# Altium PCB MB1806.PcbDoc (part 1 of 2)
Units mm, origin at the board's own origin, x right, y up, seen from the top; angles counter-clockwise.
Board outline 43.1 x 47.12 mm, 4 copper layers (Top Layer, Internal 1, Internal 2, Bottom Layer), stack 1.565 mm thick; 88 components, 68 nets, 317 pads, 562 vias.
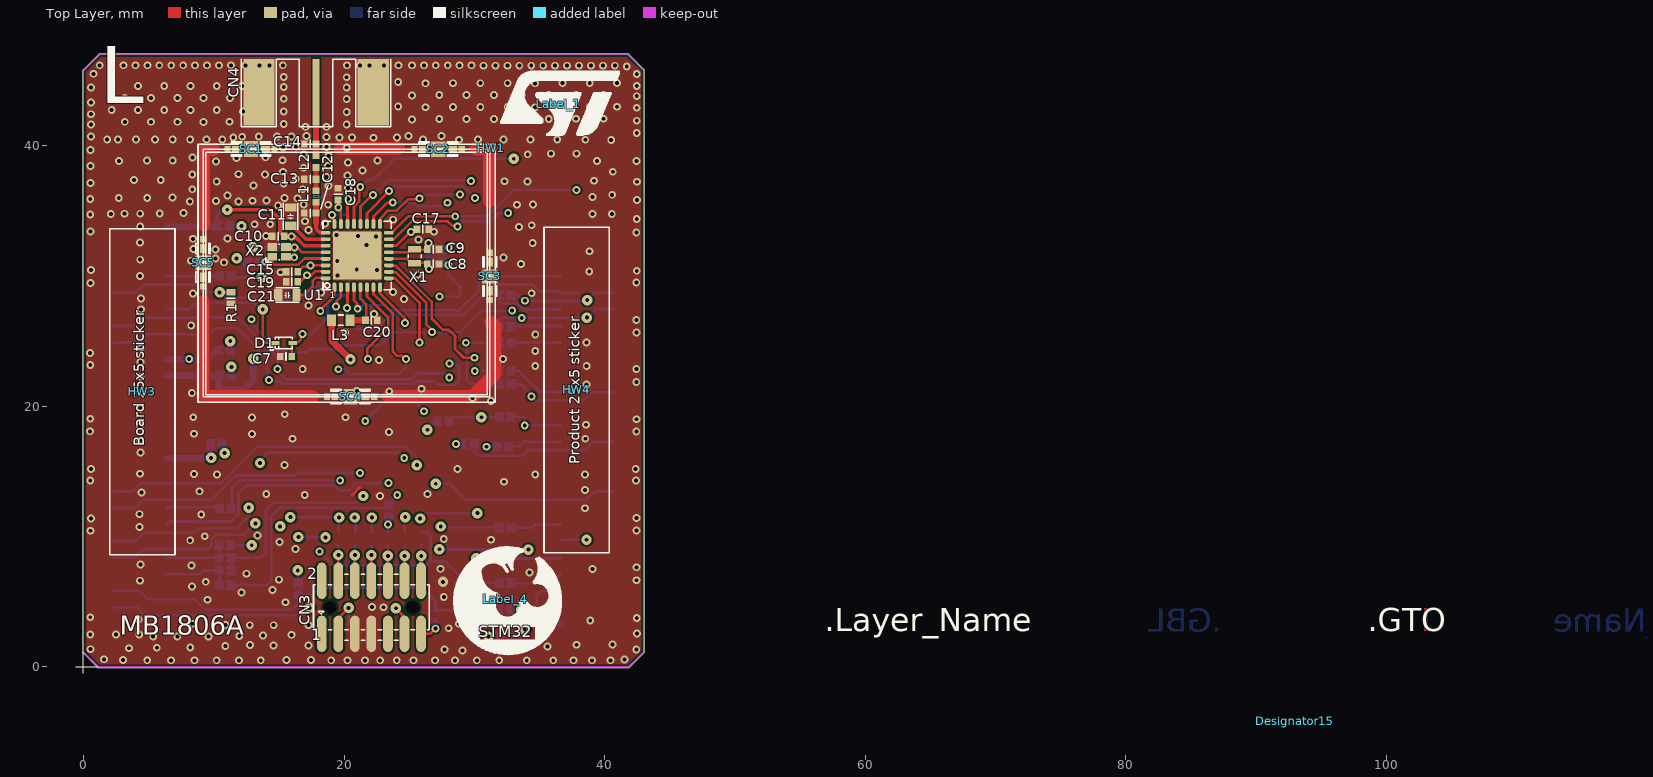
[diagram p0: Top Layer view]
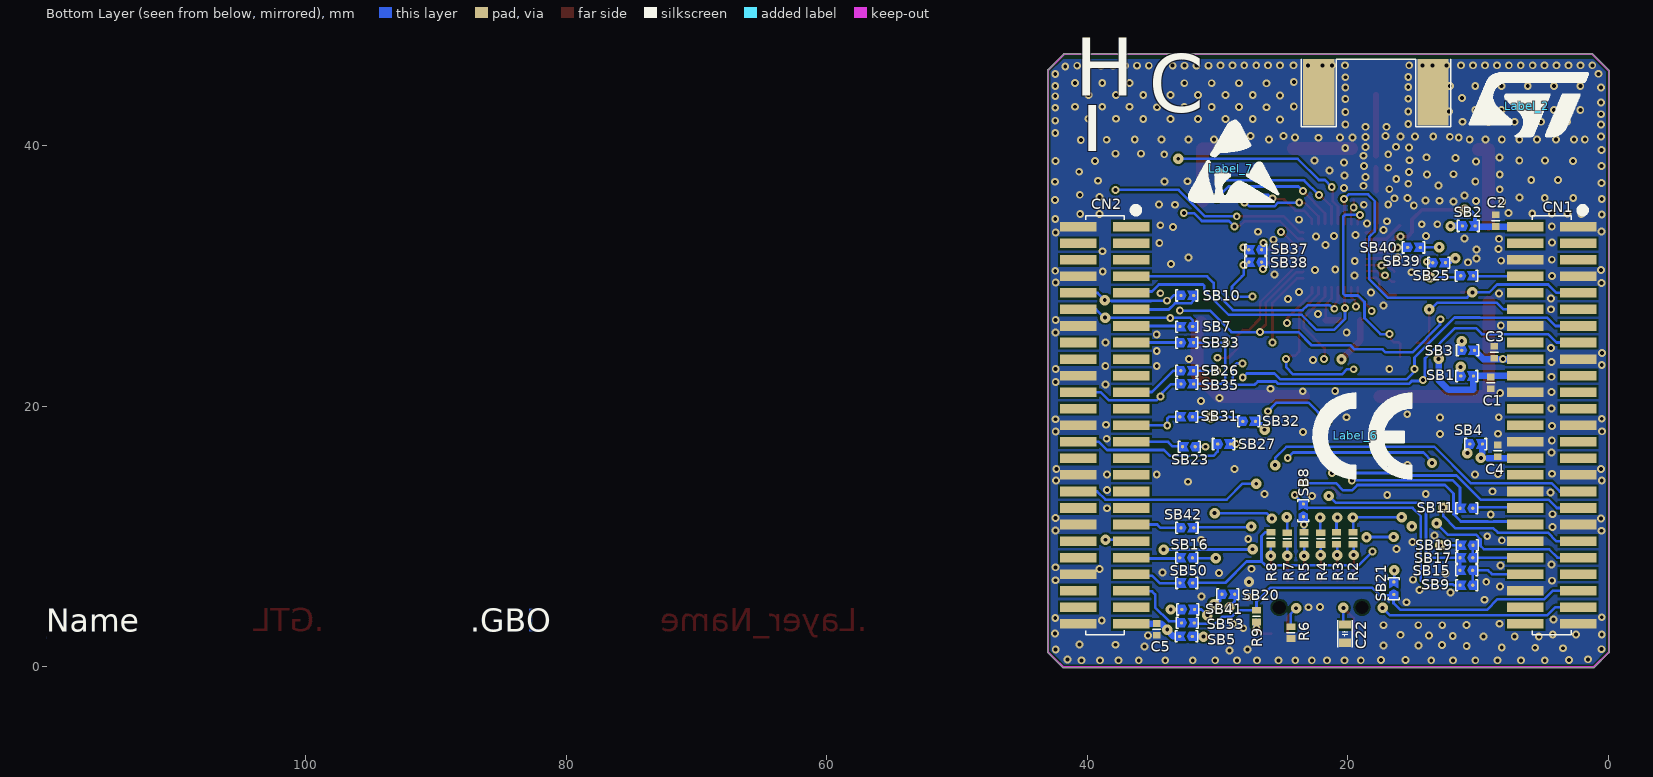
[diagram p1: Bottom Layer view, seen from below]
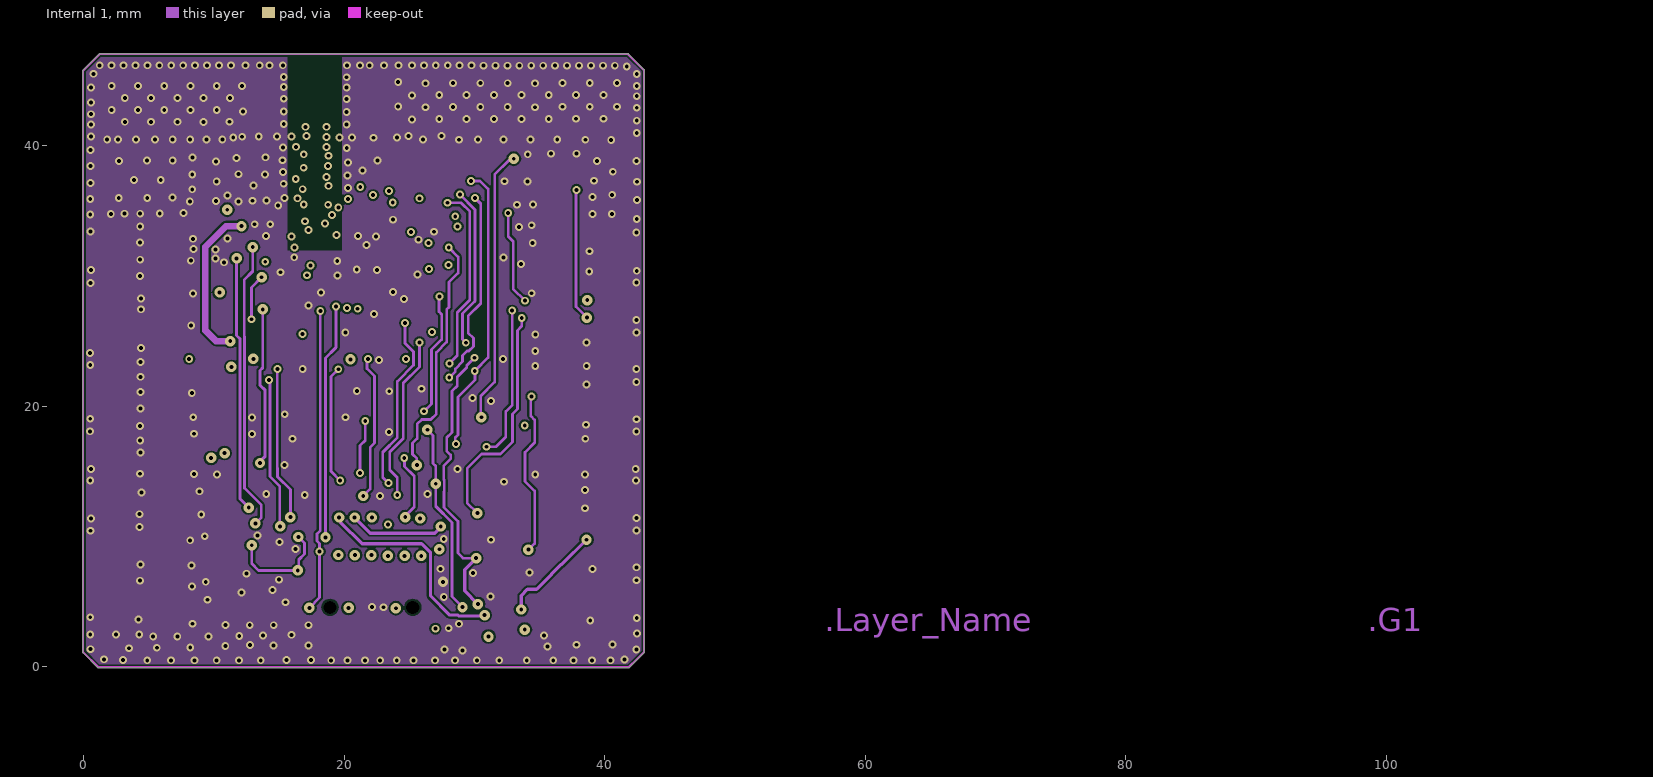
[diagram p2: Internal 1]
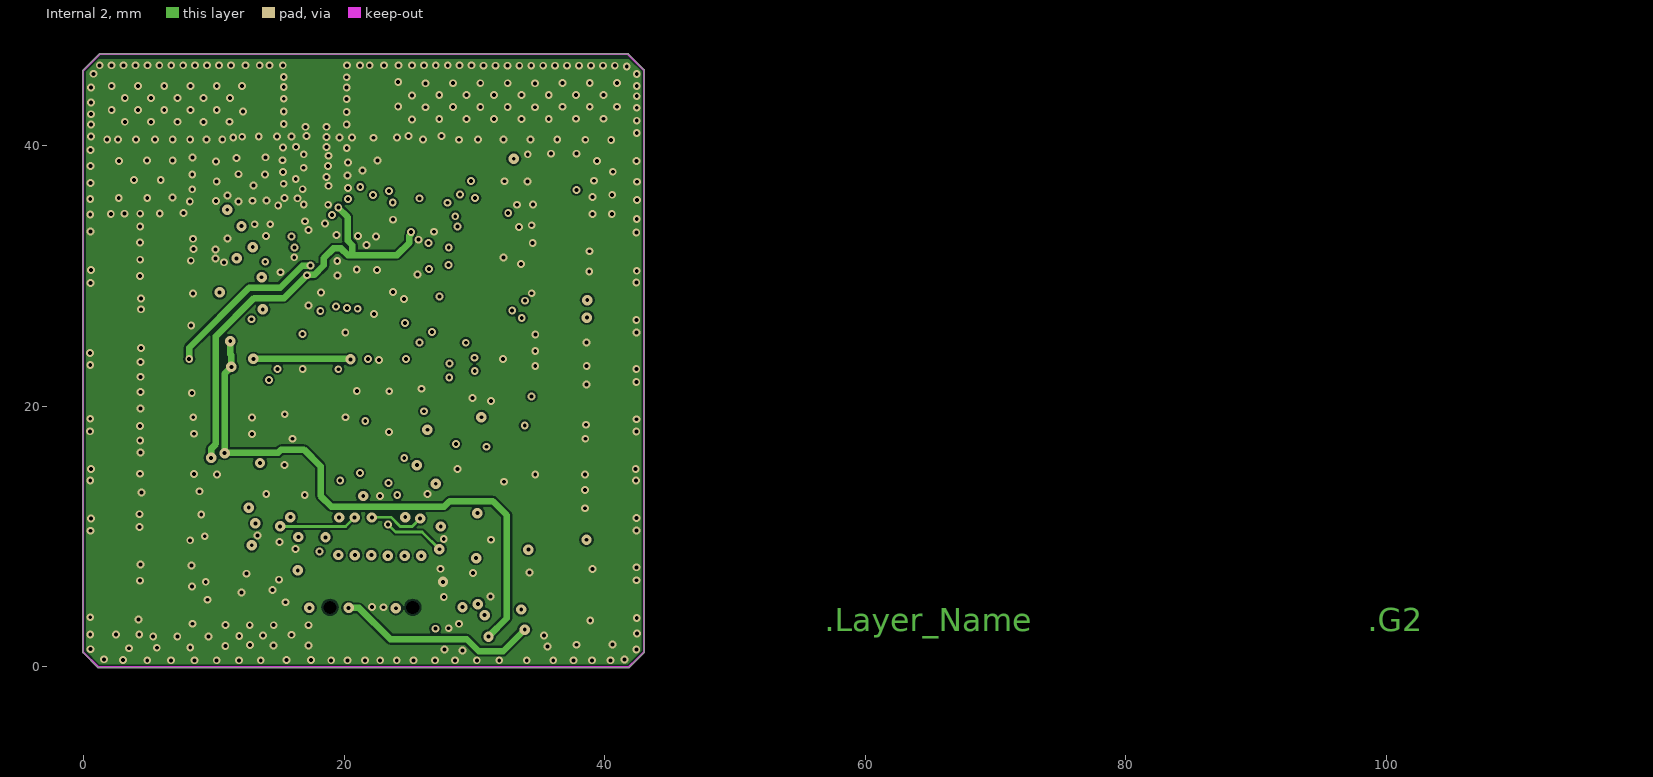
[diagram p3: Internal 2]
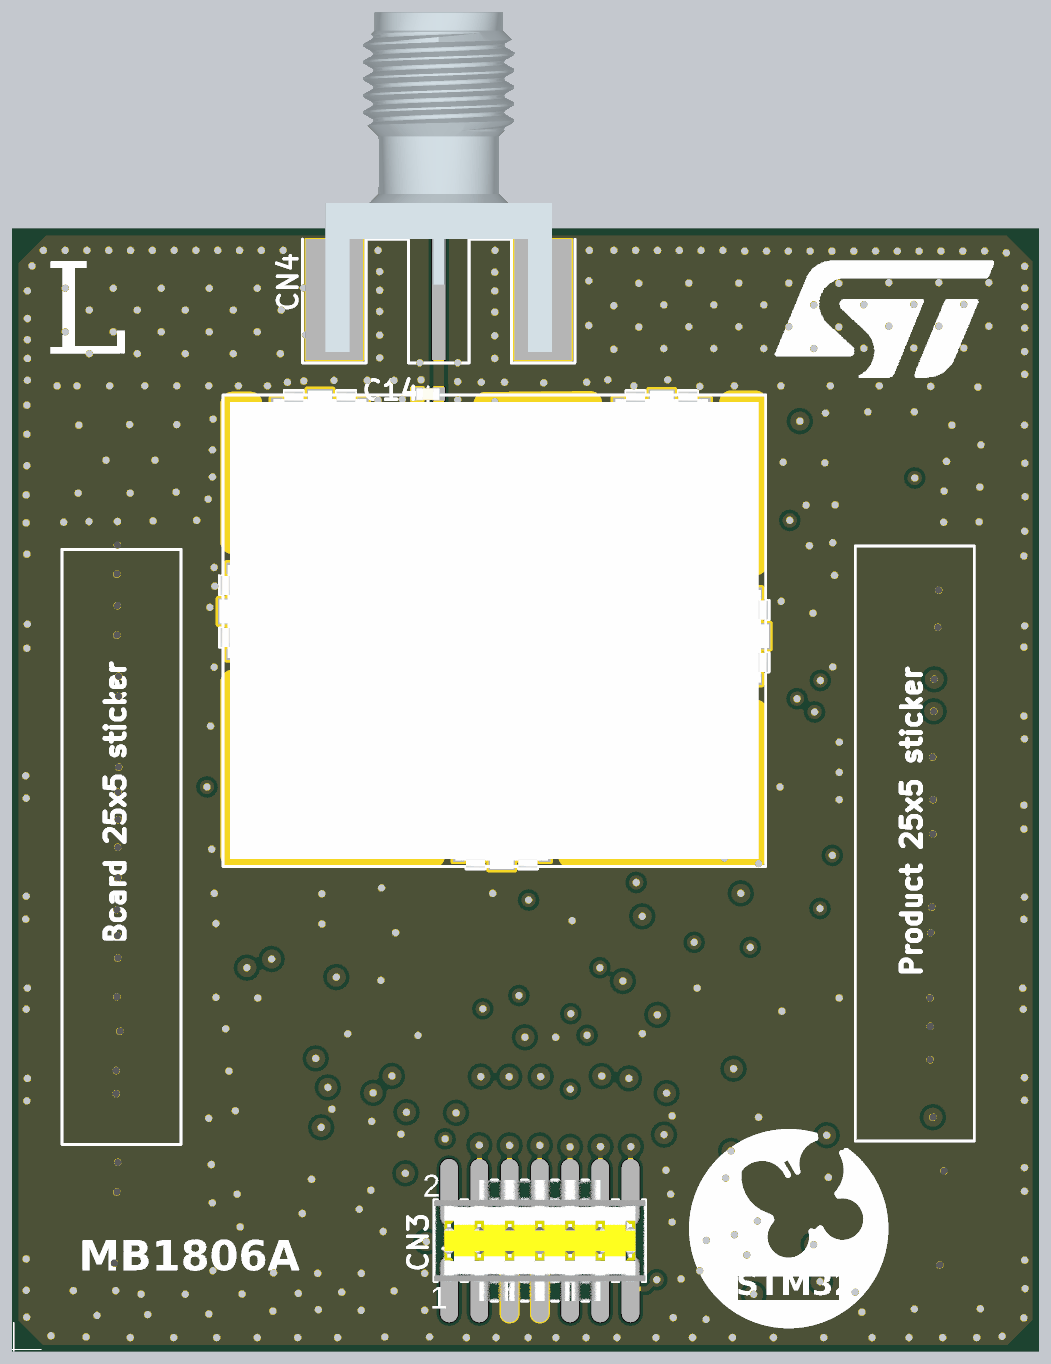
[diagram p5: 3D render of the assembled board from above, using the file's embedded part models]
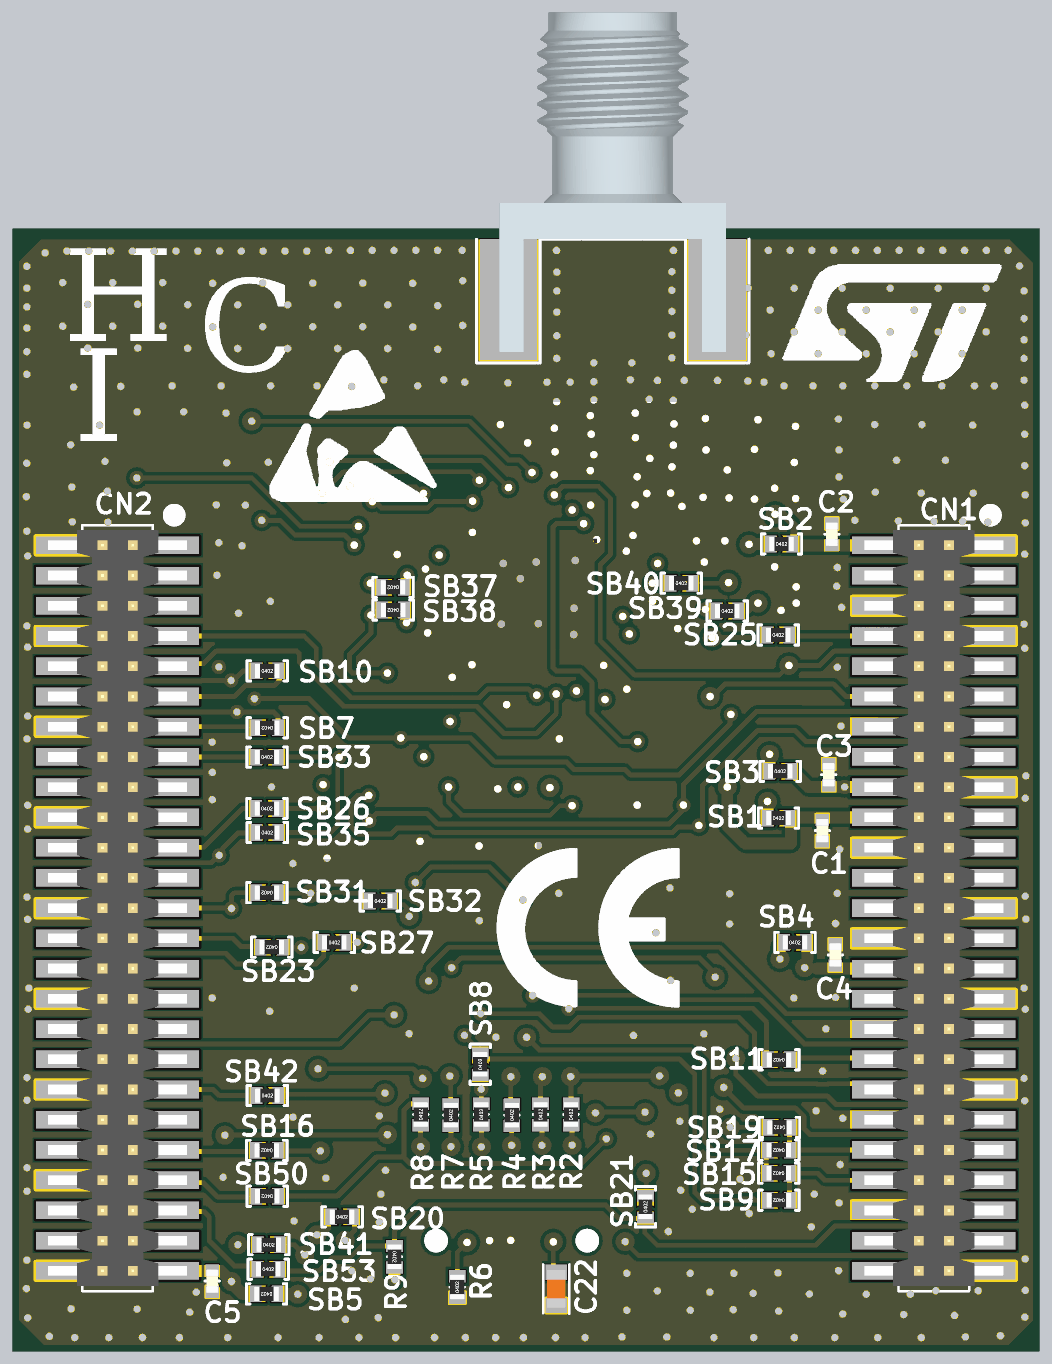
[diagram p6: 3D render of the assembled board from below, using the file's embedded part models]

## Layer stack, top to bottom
Top Solder: solder mask 0.0178, Solder Resist, Dk 4.2
Top Layer: signal copper 0.0406
Dielectric 1: core 0.0762, FR-4, Dk 3.7
Internal 1: signal copper 0.0305
Dielectric 3: prepreg 1.27, Dk 4.5
Internal 2: signal copper 0.0305
Dielectric 2: core 0.0762, Dk 3.7
Bottom Layer: signal copper 0.0406
Bottom Solder: solder mask 0.0178, Solder Resist, Dk 4.2

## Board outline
-0.036,1.103 cw(c0,1.139) -0.05,1.139 -0.05,45.75 -0.05,45.755 cw(c0,45.755) -0.035,45.791 -0.036,45.791 1.209,47.036 1.209,47.035 cw(c1.245,47) 1.245,47.05 41.326,47.066 cw(c41.326,47.015) 41.326,47.066 41.78,47.066 cw(c41.78,47.015) 41.816,47.051 42.023,46.844 43.03,45.837 cw(c43.001,45.795) 43.051,45.795 cw(c43.001,45.795) 43.05,45.785 43.05,1.151 cw(c43.001,1.141) 43.051,1.141 cw(c43.001,1.141) 43.037,1.105 41.888,-0.036 cw(c41.852,0) 41.852,-0.05 1.139,-0.05 cw(c1.139,0) 1.103,-0.036

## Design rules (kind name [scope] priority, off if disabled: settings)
Clearance "RF Path 3" [InNet('NetC12_2')] p1: gap=0.13 ignorepadtopadclearanceinfootprint=FALSE
Clearance "RF Path 2" [InNet('NetC13_2')] p2: gap=0.13 ignorepadtopadclearanceinfootprint=FALSE
Clearance "RF Path 1" [InNet('ANT')] p3: gap=0.13 ignorepadtopadclearanceinfootprint=FALSE
Clearance [All] p4: gap=0.15 ignorepadtopadclearanceinfootprint=FALSE
ComponentClearance [All] p1: gap=0.2 collisioncheckmode=3 verticalgap=0.2 showdistances=FALSE
HoleSize [All] p1: absolutevalues=TRUE maxlimit=10 minlimit=0.025 maxpercent=80.000 minpercent=20.000
MinimumSolderMaskSliver [All] p1: minsoldermaskwidth=0.05
PlaneConnect [All] p1: planeconnectstyle=Relief reliefexpansion=0.508 reliefentries=4 reliefconductorwidth=0.21 reliefairgap=0.21
PolygonConnect Path_RF [InNet('NetC12_2')] p1: connectstyle=Direct reliefconductorwidth=0.254 reliefentries=4 polygonreliefangle="90 Angle" airgapwidth=0.254
PolygonConnect PolygonConnect_via [IsVia] p2: connectstyle=Direct reliefconductorwidth=0.254 reliefentries=4 polygonreliefangle="90 Angle" airgapwidth=0.254
PolygonConnect General [All] p3: connectstyle=Direct reliefconductorwidth=0.2 reliefentries=4 polygonreliefangle="90 Angle" airgapwidth=0.2
RoutingVias [All] p1: holewidth=0.3 width=0.8 viastyle="Through Hole" minholewidth=0.2 minwidth=0.5 maxholewidth=3.5 maxwidth=6.5
SilkToSilkClearance [All] p1: silktosilkclearance=0.2
SilkToSolderMaskClearance [IsPad] p1: minsilkscreentomaskgap=0.2 clearancetoexposedcopper=TRUE
SolderMaskExpansion [All] p1: expansion=0.102 istentingtop=FALSE
Width [All] p1: maxlimit=6 minlimit=0.15 preferedwidth=0.254 toplayer_prefwidth=0.2 midlayer1_minwidth=0.21 midlayer1_maxwidth=0.512 midlayer2_minwidth=0.21 midlayer2_maxwidth=0.512 bottomlayer_prefwidth=0.2 minimp=50.000000 maximp=50.000000 favimp=50.000000
24 further rules are at their usual default settings.

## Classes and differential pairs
component class "STM32 microcontroller I/Os & Clock": C1 C2 C3 C4 C5 C7 C8 C9 CN1 CN2 D1 R1 SB1 SB2 SB3 SB4 SB5 SB7 SB8 SB9 SB10 SB11 SB15 SB16 SB17 SB19 SB20 SB21 SB23 SB25 SB26 SB27 SB31 SB32 SB33 SB35 SB37 SB38 SB39 SB40 SB41 SB42 SB50 SB53 U1 X1 X2
component class "RF & Power Management Schematic": C10 C11 C12 C13 C14 C15 C17 C18 C19 C20 C21 C22 CN3 CN4 HW1 L1 L2 L3 R2 R3 R4 R5 R6 R7 R8 R9 SC1 SC2 SC3 SC4 SC5
component class Project_Overview: HW2 HW3 HW4

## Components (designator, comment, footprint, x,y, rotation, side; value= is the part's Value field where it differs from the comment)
C1 "Capacitor" C0402 9.05,21.804 r90 bottom value=1uF
C2 "Capacitor" C0402 8.649,34.255 r270 bottom value=1uF
C3 "Capacitor" C0402 8.782,24.151 r270 bottom value=1uF
C4 "Capacitor" C0402 8.504,16.581 r270 bottom value=1uF
C5 "Capacitor" C0402 34.678,2.881 r90 bottom value=1uF
C7 "Capacitor" C0402 15.547,23.83 r0 top value=100nF
C8 "Capacitor" C0402 26.838,30.932 r180 top value=15pF
C9 "Capacitor" C0402 26.841,32.069 r180 top value=15pF
C10 "Capacitor" C0402 14.951,33.045 r180 top value=100nF
C11 "Capacitor" C0603 15.9,34.566 r270 top value=470nF
C12 "Capacitor" C0402 17.404,34.835 r0 top value=1.5pF
C13 "Capacitor" C0402 17.404,37.43 r0 top value=1.8pF
C14 "Capacitor" C0402 17.404,40.142 r0 top value=1pF
C15 "Capacitor" C0402 15.996,30.342 r180 top value=100nF
C17 "Capacitor" C0402 26.054,33.599 r0 top value=100nF
C18 "Capacitor" C0402 19.546,36.287 r90 top value=100nF
C19 "Capacitor" C0402 16.004,29.571 r180 top value=100nF
C20 "Capacitor" C0402 22.101,26.612 r180 top value=1uF
C21 "Capacitor" C0603_H0P8 15.649,28.545 r0 top value=4.7uF
C22 "Capacitor" C0603 20.231,2.554 r90 bottom value=1uF
CN1 "FTSH-125-02-L-DV" FTSH-125-02-L-DV 4.366,18.548 r180 bottom value="Header 25x2"
CN2 "FTSH-125-02-L-DV" FTSH-125-02-L-DV 38.656,18.548 r180 bottom locked value="Header 25x2"
CN3 "Header 7x2" CON_SAMTEC_FTSH-107-01-L-DV-K-A 22.101,4.579 r0 top
CN4 "SMA-J-P-H-ST-EM1" CON_SMA-RF_CINCH_142-0701-851 17.854,46.65 r0 top value=Jack_SMA_142-0701-851
D1 "SCHOTTKY_1A_2K" DIO_SOD523_1A_2K 15.384,24.869 r180 top value=BAT54KFILM
Designator14 "Comment" PCB_SPECIFICATIONS -2.234,120.134 r0 top
Designator15 "Comment" Sheetbox_4L2S 47.879,-9.525 r0 top
Designator16 "Comment" IMPEDANCE_TABLE -2.362,158.09 r0 top
HW1 "RF Shield (22.2x19.2x2mm)" SHIELD_RF_ST-CUSTOM_22P2X19P2_H2 31.293,39.802 r180 top
HW3 "STICKER_BOARD" STICKER_BOARD_25X5 4.527,21.119 r90 top value="Sticker board"
HW4 "STICKER_PRODUCT" STICKER_PRODUCT_25X5 37.849,21.262 r90 top value="Sticker product"
L1 "Inductor" C0402 17.854,36.106 r90 top value=3.3nH
L2 "Inductor" C0402 17.854,38.786 r90 top value=3.3nH
L3 "Inductor" IND_0603_H0P8 19.749,26.612 r0 top value="47R @ 100MHz"
Label_1 "LOGO_ST" LOGO_ST_Size3 36.471,43.186 r0 top
Label_2 "LOGO_ST" LOGO_ST_Size3 6.23,43.022 r180 bottom
Label_4 "LOGO_STM32" LOGO_STM32 32.4,5.201 r0 top
Label_6 "LOGO_CE" "LOGO CE" 19.419,17.729 r180 bottom
Label_7 "LOGO_ESD" "LOGO ESD" 28.979,38.255 r180 bottom
R1 "Resistor" R0402 11.319,28.312 r270 top value=100K
R2 "Resistor" R0402 19.605,9.878 r90 bottom value=47R
R3 "Resistor" R0402 20.887,9.878 r90 bottom value=47R
R4 "Resistor" R0402 22.092,9.852 r90 bottom value=47R
R5 "Resistor" R0402 23.376,9.878 r90 bottom value=47R
R6 "Resistor" R0402 24.386,2.631 r90 bottom value=47R
R7 "Resistor" R0402 24.658,9.853 r90 bottom value=47R
R8 "Resistor" R0402 25.922,9.878 r90 bottom value=47R
R9 "Resistor" R0402 27.024,3.9 r270 bottom value=47R
SB1 "SB_OFF" SOLDER-BRIDGE_R0402-0R 10.893,22.329 r180 bottom
SB2 "SB_OFF" SOLDER-BRIDGE_R0402-0R 10.764,33.846 r180 bottom
SB3 "SB_OFF" SOLDER-BRIDGE_R0402-0R 10.819,24.295 r180 bottom
SB4 "SB_OFF" SOLDER-BRIDGE_R0402-0R 10.201,17.107 r180 bottom
SB5 "SB_OFF" SOLDER-BRIDGE_R0402-0R 32.397,2.343 r0 bottom
SB7 "SB_ON" SOLDER-BRIDGE_R0402-0R 32.372,26.123 r0 bottom
SB8 "SB_OFF" SOLDER-BRIDGE_R0402-0R 23.421,11.984 r90 bottom
SB9 "SB_ON" SOLDER-BRIDGE_R0402-0R 10.875,6.277 r0 bottom
SB10 "SB_ON" SOLDER-BRIDGE_R0402-0R 32.367,28.514 r180 bottom
SB11 "SB_ON" SOLDER-BRIDGE_R0402-0R 10.874,12.177 r0 bottom
SB15 "SB_OFF" SOLDER-BRIDGE_R0402-0R 10.885,7.413 r0 bottom
SB16 "SB_ON" SOLDER-BRIDGE_R0402-0R 32.385,8.371 r0 bottom
SB17 "SB_ON" SOLDER-BRIDGE_R0402-0R 10.878,8.381 r0 bottom
SB19 "SB_OFF" SOLDER-BRIDGE_R0402-0R 10.85,9.337 r0 bottom
SB20 "SB_OFF" SOLDER-BRIDGE_R0402-0R 29.225,5.579 r180 bottom
SB21 "SB_ON" SOLDER-BRIDGE_R0402-0R 16.481,6.002 r90 bottom
SB23 "SB_ON" SOLDER-BRIDGE_R0402-0R 32.178,16.908 r0 bottom
SB25 "SB_OFF" SOLDER-BRIDGE_R0402-0R 10.902,30.022 r180 bottom
SB26 "SB_ON" SOLDER-BRIDGE_R0402-0R 32.383,22.731 r180 bottom
SB27 "SB_OFF" SOLDER-BRIDGE_R0402-0R 29.549,17.107 r180 bottom
SB31 "SB_ON" SOLDER-BRIDGE_R0402-0R 32.382,19.199 r0 bottom
SB32 "SB_OFF" SOLDER-BRIDGE_R0402-0R 27.619,18.845 r180 bottom
SB33 "SB_ON" SOLDER-BRIDGE_R0402-0R 32.377,24.893 r180 bottom
SB35 "SB_OFF" SOLDER-BRIDGE_R0402-0R 32.367,21.723 r180 bottom
SB37 "SB_OFF" SOLDER-BRIDGE_R0402-0R 27.084,32.023 r0 bottom
SB38 "SB_OFF" SOLDER-BRIDGE_R0402-0R 27.08,31.069 r0 bottom
SB39 "SB_OFF" SOLDER-BRIDGE_R0402-0R 13.043,31.029 r180 bottom
SB40 "SB_OFF" SOLDER-BRIDGE_R0402-0R 14.974,32.198 r180 bottom
SB41 "SB_OFF" SOLDER-BRIDGE_R0402-0R 32.303,4.41 r180 bottom
SB42 "SB_OFF" SOLDER-BRIDGE_R0402-0R 32.363,10.674 r180 bottom
SB50 "SB_ON" SOLDER-BRIDGE_R0402-0R 32.372,6.445 r0 bottom
SB53 "SB_OFF" SOLDER-BRIDGE_R0402-0R 32.327,3.379 r180 bottom
SC1 "Shield-clip_S0951-46R" CLIP_HARWIN_S0951-46R#1 12.862,39.742 r180 top value=S0951-46R
SC2 "Shield-clip_S0951-46R" CLIP_HARWIN_S0951-46R#2 27.222,39.742 r180 top value=S0951-46R
SC3 "Shield-clip_S0951-46R" CLIP_HARWIN_S0951-46R#2 31.182,29.971 r90 top value=S0951-46R
SC4 "Shield-clip_S0951-46R" CLIP_HARWIN_S0951-46R#2 20.502,20.745 r180 top value=S0951-46R
SC5 "Shield-clip_S0951-46R" CLIP_HARWIN_S0951-46R#2 9.185,31.013 r90 top value=S0951-46R
U1 "STM32WBA54KGU6" ICC_UFQFPN32-EPAD_5X5_P050 21.014,31.575 r0 top
X1 "XTAL_2_PINS" CRY_NX1610SE_2P 25.421,31.523 r270 top value=32.768kHz
X2 "XTAL_4_PINS" CRY_NX1612SA_4P 15.026,31.855 r0 top value=32MHz

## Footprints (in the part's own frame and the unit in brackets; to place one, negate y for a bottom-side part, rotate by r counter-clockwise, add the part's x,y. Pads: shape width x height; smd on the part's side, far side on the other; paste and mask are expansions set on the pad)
C0402 [mm]
  rect 0.51x0.56 smd mask+0.05: 1(-0.45,0) 2(0.45,0)
  silkscreen extent 0,-0.3 0,0.3, body extent -0.5,-0.3 0.5,0.3, height 0.4
C0603 [mm]
  rect 0.64x0.89 smd mask+0.05: 1(-0.7,0) 2(0.7,0)
  silkscreen extent -1.05,-0.55 1.02,0.55, body extent -0.9,-0.5 0.9,0.5, height 1.4
C0603_H0P8 [mm] "MCD-01540"
  rect 0.64x0.89 smd mask+0.05: 1(-0.7,0) 2(0.7,0)
  silkscreen extent -0.9,-0.55 0.9,0.55, body extent -0.9,-0.5 0.9,0.5, height 1
CLIP_HARWIN_S0951-46R#1 [mm] "MCD-01587_CLIP-X1"
  rect 0.48x0.5 smd mask+0.1: 1(-1.81,0) 1(1.81,0)
  rect 0.7x0.5 smd mask+0.1: 1(-1.1,0) 1(1.1,0)
  rect 1.1x1.2 smd mask+0.1: 1(0,-0.013)
  silkscreen extent -1.5,-0.55 1.5,0.55, body extent -2.05,-0.65 2.05,0.65, height 1.28
CLIP_HARWIN_S0951-46R#2 [mm] "MCD-01587_CLIP-X1"
  rect 0.48x0.5 smd mask+0.1: 1(-1.81,0) 1(1.81,0)
  rect 0.7x0.5 smd mask+0.1: 1(-1.1,0) 1(1.1,0)
  rect 1.1x1.2 smd mask+0.1: 1(0,0)
  silkscreen extent -1.5,-0.55 1.5,0.55, body extent -2.05,-0.65 2.05,0.65, height 1.28
CON_SAMTEC_FTSH-107-01-L-DV-K-A [mm] "MCD-01959"
  oval 0.74x2.79 smd mask+0.05: 1(-3.81,-2.035) 2(-3.81,2.035) 3(-2.54,-2.035) 4(-2.54,2.035) 5(-1.27,-2.035) 6(-1.27,2.035) 7(0,-2.035) 8(0,2.035) 9(1.27,-2.035) 10(1.27,2.035) 11(2.54,-2.035) 12(2.54,2.035) 13(3.81,-2.035) 14(3.81,2.035)
  round 0 hole 1 unplated paste-10 mask+0.05: NPTH1(-3.175,0) NPTH2(3.175,0)
  silkscreen extent -4.44,-2.54 4.44,2.54, body extent -4.44,-2.92 4.45,2.92, height 6.12
CON_SMA-RF_CINCH_142-0701-851 [mil] "MCD-02072"
  rect 21.65x200 smd mask+1.97: 1(0,-100)
  rect 95x200 smd mask+1.97: 2(172.48,-100) 3(-172.48,-100)
  rect 95x200 smd far side mask+1.97: 4(-172.48,-100) 5(172.48,-100)
  silkscreen extent -225,-205 225,0, body extent -189,-187 189,376, height 161
CRY_NX1610SE_2P [mm] "MCD-02291"
  rect 0.5x1 smd mask+0.05: 1(-0.55,0) 2(0.55,0)
  silkscreen extent -0.13,-0.5 0.13,0.5, body extent -0.8,-0.5 0.8,0.5, height 0.45
CRY_NX1612SA_4P [mm] "MCD-02262"
  rect 0.75x0.6 smd mask+0.038: 1(-0.525,-0.375) 2(0.525,-0.375) 3(0.525,0.375) 4(-0.525,0.375)
  silkscreen extent -1.02,-0.8 0.03,0.6, body extent -0.8,-0.6 0.8,0.6, height 0.51
DIO_SOD523_1A_2K [mm] "MCD-01677"
  rect 0.65x0.3 smd mask+0.05: 1(-0.675,0) 2(0.675,0)
  silkscreen extent -0.65,-0.45 1.05,0.55, body extent -0.85,-0.45 0.85,0.45, height 0.71
FTSH-125-02-L-DV [mil] "Header2x25 Reverse 1.27mm SAMTEC (FTSH-125-02-L-DV)"
  rect 110x29.02 smd: 1(80,600) 2(-80,600) 3(80,550) 4(-80,550) 5(80,500) 6(-80,500) 7(80,450) 8(-80,450) 9(80,400) 10(-80,400) 11(80,350) 12(-80,350) 13(80,300) 14(-80,300) 15(80,250) 16(-80,250) 17(80,200) 18(-80,200) 19(80,150) 20(-80,150) 21(80,100) 22(-80,100) 23(80,50) 24(-80,50) 25(80,0) 26(-80,0) 27(80,-50) 28(-80,-50) 29(80,-100) 30(-80,-100) 31(80,-150) 32(-80,-150) 33(80,-200) 34(-80,-200) 35(80,-250) 36(-80,-250) 37(80,-300) 38(-80,-300) 39(80,-350) 40(-80,-350) 41(80,-400) 42(-80,-400) 43(80,-450) 44(-80,-450) 45(80,-500) 46(-80,-500) 47(80,-550) 48(-80,-550) 49(80,-600) 50(-80,-600)
  silkscreen extent -58,-633 103,659, body extent -115,-625 115,625, height 190
ICC_UFQFPN32-EPAD_5X5_P050 [mm] "MCD-01398"
  oval 0.3x0.75 smd mask+0.05: 1(-1.75,-2.425) 2(-1.25,-2.425) 3(-0.75,-2.425) 4(-0.25,-2.425) 5(0.25,-2.425) 6(0.75,-2.425) 7(1.25,-2.425) 8(1.75,-2.425) 17(1.75,2.425) 18(1.25,2.425) 19(0.75,2.425) 20(0.25,2.425) 21(-0.25,2.425) 22(-0.75,2.425) 23(-1.25,2.425) 24(-1.75,2.425)
  oval 0.75x0.3 smd mask+0.05: 9(2.425,-1.75) 10(2.425,-1.25) 11(2.425,-0.75) 12(2.425,-0.25) 13(2.425,0.25) 14(2.425,0.75) 15(2.425,1.25) 16(2.425,1.75) 25(-2.425,1.75) 26(-2.425,1.25) 27(-2.425,0.75) 28(-2.425,0.25) 29(-2.425,-0.25) 30(-2.425,-0.75) 31(-2.425,-1.25) 32(-2.425,-1.75)
  rect 3.7x3.7 smd mask+0.05: 33(0,0)
  silkscreen extent -2.63,-2.63 2.63,2.63, body extent -2.55,-2.55 2.55,2.55, height 0.6
IMPEDANCE_TABLE [mm]
IND_0603_H0P8 [mm]
  rect 0.7x0.9 smd mask+0.05: 1(-0.7,0) 2(0.7,0)
  silkscreen extent -0.2,-0.4 0.2,0.4, body extent -0.8,-0.4 0.8,0.4, height 0.8
"LOGO CE" [mm]
  silkscreen extent -3.27,-3.31 4.33,3.3
"LOGO ESD" [mm]
  silkscreen extent -3.23,-2.59 3.66,3.68
LOGO_ST_Size3 [mm]
  silkscreen extent -4.5,-2.36 4.7,2.57
LOGO_STM32 [mm]
  silkscreen extent -3.9,-4.23 4.33,3.95
PCB_SPECIFICATIONS [mm]
R0402 [mm]
  rect 0.51x0.7 smd mask+0.05: 1(-0.45,0) 2(0.45,0)
  silkscreen extent 0,-0.3 0,0.3, body extent -0.52,-0.3 0.52,0.3, height 0.4
Sheetbox_4L2S [mil] "Sheetbox 4 layers / 2 silkscreens"
  round 20 on Mech16: 1(813.78,210.69) 1(2736.9,210.69)
SHIELD_RF_ST-CUSTOM_22P2X19P2_H2 [mm] "MCD-02088"
  silkscreen extent -0.3,-0.3 22.5,19.5, body extent 0,0 22.2,19.2, height 2.45
SOLDER-BRIDGE_R0402-0R [mil] "MCD-01619"
  round 10 smd paste-393.7: 1(-17.72,0) 2(20.67,0)
  Top Layer region: -30.51,-13.78 -30.51,13.78 -8.37,13.78 -1.48,0 -8.37,-13.78
  Top Layer region: 1.48,13.78 8.37,0 1.48,-13.78 30.51,-13.78 30.51,13.78
  silkscreen extent -33,-17 33,17, body extent -20,-12 20,12, height 14
STICKER_BOARD_25X5 [mm] "Sticker to mention board reference + serial number"
  silkscreen extent -12.5,-2.5 12.5,2.5, body extent -12.5,-2.5 12.5,2.5, height 0.01
STICKER_PRODUCT_25X5 [mm] "Sticker to mention board CPN code"
  silkscreen extent -12.5,-2.5 12.5,2.5

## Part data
C1 C2 C3 C4 C5 C20: library part MCD-01722, "Capacitor, MLCC, 1uF, 10V, X5R, +/-10%, 0402, T=0.5mm", Manufacturer=YAGEO, Manufacturer_Part_Number=CC0402KRX5R6BB105, Package=0402
C7 C10 C15 C17 C18 C19: library part MCD-00006, "Capacitor, MLCC, 100nF, 16V, X7R, +/-10%, 0402, T=0.5mm", Alternate_Manufacturer=MURATA, Alternate_Manufacturer_Part_Number=GCM155R71C104KA55D, Manufacturer=YAGEO, Manufacturer_Part_Number=CC0402KRX7R7BB104, Package=C0402
C8 C9: library part MCD-01933, "Capacitor, MLCC, 15pF, 50V, NPO, +/-2%, 0402, T=0.5mm", Manufacturer=YAGEO, Manufacturer_Part_Number=CC0402GRNPO9BN150, Package=0402
C11: library part MCD-01006, "Capacitor, MLCC, 470nF, 16V, X7R, +/-10%, 0603, T=0.8mm", Manufacturer=YAGEO, Manufacturer_Part_Number=CC0603KRX7R7BB474, Package=0603
C12: library part MCD-02994, "Capacitor, MLCC, 1.5pF, 50V, C0G, +/-0.25pF, 0402, T=0.5mm", Manufacturer=MURATA, Manufacturer_Part_Number=GRM1555C1H1R5CA01, Package=0402
C13: library part MCD-02995, "Capacitor, MLCC, 1.8pF, 50V, C0G, +/-0.25pF, 0402, T=0.5mm", Manufacturer=MURATA, Manufacturer_Part_Number=GRM1555C1H1R8CA01, Package=0402
C14: library part MCD-03045, "Capacitor, MLCC, 1.0pF, 50V, C0G, +/-0.25pF, 0402, T=0.5mm", Manufacturer=MURATA, Manufacturer_Part_Number=GRM1555C1H1R0CA01, Package=0402
C21: library part MCD-01721, "Capacitor, MLCC, 4.7uF, 10V, X5R, +/-10%, 0603, T=0.8mm", Manufacturer=YAGEO, Manufacturer_Part_Number=CC0603KRX5R6BB475, Package=0603
C22: library part MCD-00010, "Capacitor, MLCC, 1uF, 16V, X5R, 10%, 0603, T=0,8mm", Manufacturer=YAGEO, Manufacturer_Part_Number=CC0603KRX5R7BB105, Package=C0603
CN1 CN2: library part MCD-02746, "Header, 25x2, 12.7mm, VR, SMD, T=4.83mm", Manufacturer=SAMTEC
CN3: library part MCD-01531, "Header, 7x2, 1.27mm, VR, T=5.97mm, FTSH series STDC14 without Alignment Pin", Manufacturer=SAMTEC, Manufacturer_Part_Number=FTSH-107-01-L-DV-K
CN4: library part MCD-02072, "Jack_SMA, VR, PCB edge, 50R, T=7.92mm", Alternate_Manufacturer=N/A, Manufacturer=JOHNSON, Manufacturer_Part_Number=142-0701-851
D1: library part MCD-01677, "Small signal Schottky diodes", Manufacturer=STMICROELECTRONICS, Manufacturer_HQ_COO=EU, Manufacturer_Part_Number=BAT54KFILM, Package=SOD-523
Designator14 Designator15 Designator16: library part MCD-00279
HW1: library part MCD-03256, Manufacturer=TBD
HW3: library part MCD-02190, "Sticker board 25x5 mm", Alternate_Manufacturer=N/A
HW4: library part MCD-02189, "Sticker product 25x5 mm", Alternate_Manufacturer=N/A
L1 L2: library part MCD-03001, "Inductor, 3.3nH, +/-0.3nH, 800 mA, 0.125Ohm, 0402, T=0.5mm", Manufacturer=MURATA, Manufacturer_Part_Number=LQG15HS3N3S02, Package=0402
L3: library part MCD-02587, "Ferrite bead, 47R @ 100MHz, +/-25%, 3.5A, 0R02, 0603, T=0.8mm", Manufacturer="TAIYO YUDEN", Manufacturer_Part_Number=FBMH1608HM470-T, Package=0603
R1: library part MCD-00059, "Resistor, 100K, 0402, +/-1%, 1/16W", Manufacturer=YAGEO, Manufacturer_Part_Number=RC0402FR-07100KL, Package=0402
R2 R3 R4 R5 R6 R7 R8 R9: library part MCD-00481, "Resistor,47R,0402,1%,1/16W", Manufacturer=YAGEO, Manufacturer_Part_Number=RC0402FR-0747RL, Package=R0402
SB1 SB2 SB3 SB4 SB5 SB8 SB15 SB19 SB20 SB25 SB27 SB32 SB35 SB37 SB38 SB39 SB40 SB41 SB42 SB53: library part MCD-02162, "Solder Bridge 0402 OFF", Manufacturer=YAGEO, Manufacturer_Part_Number=RC0402JR-070RL, Package=SB0402
SB7 SB9 SB10 SB11 SB16 SB17 SB21 SB23 SB26 SB31 SB33 SB50: library part MCD-01618, "Solder Bridge 0402 ON", Manufacturer=YAGEO, Manufacturer_Part_Number=RC0402JR-070RL, Package=SB0402
SC1 SC2 SC3 SC4 SC5: library part MCD-01587, "shield clip Harwin S0951-46R to fix RF shielded cavity", Manufacturer=HARWIN, Manufacturer_Part_Number=S0951-46R
U1: library part MCD-02744, "MCU, ARM Cortex-M33 32-bit, 1MB Flash, 128KB SRAM, With Crypto", Manufacturer=STMICROELECTRONICS, Package=UFQFPN32
X1: library part MCD-02579, "Crystal, 32.768kHz, 6pF, +/-20ppm, 70KR, 1.6x1mm", Manufacturer=NDK, Manufacturer_Part_Number=NX1610SE-32.768KHZ-EXS00A-MU01501, Package=1.6x1mm
X2: library part MCD-02578, "Crystal, 32MHz, 8pF, +/-10ppm, 40R, 1612(metric), T=0.3mm", Manufacturer=NDK, Manufacturer_Part_Number=NX1612SA-32MHZ-EXS00A-CS09166, Package=1612(metric)

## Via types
v1: diameter 0.6, hole 0.3, Top Layer to Bottom Layer, tented both sides, 505 vias
v2: diameter 0.8, hole 0.3, Top Layer to Bottom Layer, tented both sides, 57 vias

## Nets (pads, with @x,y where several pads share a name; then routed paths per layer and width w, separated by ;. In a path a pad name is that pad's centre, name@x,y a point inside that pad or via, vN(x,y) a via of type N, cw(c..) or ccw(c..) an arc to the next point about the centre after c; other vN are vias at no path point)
GND: C1.1 C2.1 C3.1 C4.1 C5.1 C7.1 C8.1 C9.1 C10.2 C11.1 C12.1 C13.1 C14.1 C15.2 C17.2 C18.2 C19.2 C20.1 C21.1 C22.1 CN1.1 CN1.6 CN1.7 CN1.14 CN1.17 CN1.22 CN1.25 CN1.28 CN1.31 CN1.34 CN1.37 CN1.40 CN1.46 CN1.49 CN2.2 CN2.8 CN2.14 CN2.20 CN2.26 CN2.32 CN2.38 CN2.44 CN2.50 CN3.5 CN3.7 CN4.2 CN4.3 CN4.4 CN4.5 R1.2 R6.1 SC1.1 SC2.1 SC3.1 SC4.1 SC5.1 U1.33 X2.2 X2.4 | length 45.8
  Top Layer w0.2: 20.634,13.199 21.207,13.772 ; 22.447,13.199 22.687,13.199 v1(22.764,13.122)
  Top Layer w1: 9.185,28.007 9.185,20.745 17.539,20.745 ; 9.21,33.949 9.21,39.718 9.995,39.718 ; 19.749,39.783 24.194,39.775 ; 23.432,20.742 29.858,20.742 31.597,22.482 31.597,26.132 31.289,26.44 ; 30.137,39.767 31.179,39.767 31.179,35.774
  other v1: 4.894,0.508 6.723,0.508 8.527,0.508 10.228,0.508 11.93,0.508 13.607,0.508 19.017,0.508 20.261,0.508 21.608,0.508 22.776,0.508 24.046,0.508 25.341,0.508 26.978,0.508 28.516,0.508 30.193,0.508 31.916,0.508 34.028,0.508 36.06,0.508 37.61,0.508 39.024,0.508 40.454,0.508 3.04,0.533 15.588,0.533 17.467,0.533 41.521,0.559 1.567,0.584 29.085,1.27 27.707,1.346 42.436,1.337 0.546,1.362 3.497,1.437 5.631,1.473 8.196,1.499 35.628,1.575 10.889,1.618 14.597,1.651 17.264,1.651 12.794,1.676 37.838,1.702 40.607,1.716 5.352,2.327 7.206,2.327 9.593,2.337 11.956,2.362 13.778,2.413 35.349,2.413 15.98,2.464 0.526,2.489 2.507,2.478 4.284,2.478 42.486,2.565 28.034,2.972 10.914,3.226 12.768,3.205 14.602,3.205 17.264,3.205 8.37,3.318 28.819,3.308 38.899,3.554 4.229,3.634 42.467,3.761 0.526,3.81 22.141,4.588 23.03,4.579 15.521,4.963 9.513,5.155 27.66,5.359 31.242,5.404 12.123,5.72 14.514,5.896 8.344,6.163 9.386,6.532 4.331,6.62 42.461,6.655 15.004,6.696 12.51,7.158 29.908,7.204 34.226,7.238 39.078,7.509 27.402,7.532 42.461,7.645 8.301,7.777 4.372,7.865 16.269,9.052 15.038,9.588 8.192,9.719 31.289,9.764 27.657,9.82 9.314,10.033 13.365,10.1 0.551,10.453 42.461,10.475 4.306,10.75 0.576,11.395 42.461,11.43 9.042,11.7 4.306,11.725 38.494,12.182 16.984,13.199 14.03,13.264 26.412,13.275 4.458,13.376 8.903,13.478 38.505,13.58 32.271,14.215 0.526,14.3 42.41,14.3 10.249,14.773 34.678,14.773 38.494,14.776 8.496,14.798 4.331,14.824 0.576,15.189 28.713,15.189 42.385,15.189 15.424,15.51 4.372,16.45 4.356,17.39 16.041,17.514 38.522,17.514 12.946,17.882 8.496,17.9 23.458,18.025 0.5,18.085 42.436,18.074 4.331,18.482 38.566,18.589 42.461,19.013 0.526,19.05 12.946,19.152 8.425,19.166 20.122,19.166 15.451,19.396 4.382,19.828 31.293,20.422 29.858,20.641 8.319,21.022 4.372,21.098 23.471,21.157 20.982,21.174 25.951,21.354 38.621,21.666 42.436,21.869 4.382,22.266 16.828,22.877 42.436,22.871 34.678,23.102 38.626,23.107 0.526,23.165 4.382,23.409 22.685,23.556 32.191,23.638 0.5,24.106 34.678,24.248 4.407,24.476 38.6,24.893 34.684,25.518 20.099,25.659 42.461,25.659 8.268,26.194 42.436,26.617 22.312,27.094 4.407,27.448 17.264,27.744 24.6,28.244 4.407,28.286 8.42,28.667 34.405,28.68 18.236,28.743 23.767,28.774 0.551,29.464 42.436,29.515 4.331,30.013 19.494,30.042 25.63,30.109 15.126,30.293 38.82,30.339 42.467,30.404 0.576,30.476 22.533,30.476 20.978,30.497 33.576,30.937 10.785,31.057 19.48,31.145 8.243,31.182 4.356,31.258 10.148,31.36 16.184,31.44 32.24,31.436 38.852,31.902 10.148,32.045 8.446,32.071 21.734,32.388 34.481,32.528 4.331,32.579 25.722,32.794 8.42,32.858 11.055,32.884 22.456,33.026 14.008,33.087 21.072,33.087 19.431,33.153 42.436,33.341 0.551,33.417 26.908,33.403 17.285,33.544 33.428,33.773 4.356,33.798 34.405,33.9 13.145,33.976 14.339,33.976 18.53,34.027 17.006,34.204 23.751,34.33 42.467,34.38 0.521,34.733 2.1,34.759 39.066,34.759 40.556,34.773 3.163,34.789 4.356,34.789 5.855,34.814 7.684,34.835 14.948,35.424 18.784,35.474 33.286,35.474 16.912,35.49 34.506,35.487 8.166,35.728 11.9,35.728 10.173,35.754 12.967,35.779 14.059,35.805 42.486,35.832 0.526,35.906 16.426,35.966 2.71,35.982 4.894,35.982 15.424,35.982 6.825,36.023 39.083,36.068 11.055,36.186 40.581,36.236 8.349,36.66 16.828,36.67 20.312,36.751 18.798,36.928 13.043,36.957 15.368,37.084 0.551,37.135 42.477,37.236 34.074,37.252 10.228,37.27 32.322,37.278 39.184,37.313 3.878,37.363 5.936,37.363 16.299,37.44 18.65,37.597 20.277,37.719 8.349,37.795 13.937,37.795 11.9,37.821 15.308,37.998 40.632,38.01 21.43,38.092 16.904,38.311 0.551,38.456 18.76,38.456 20.308,38.71 10.178,38.786 2.735,38.837 39.413,38.837 42.461,38.837 4.869,38.862 6.85,38.862 22.576,38.862 15.283,38.887 11.753,39.065 8.374,39.091 13.962,39.116 18.798,39.236 16.912,39.345 34.101,39.345 35.882,39.395 37.838,39.395 0.551,39.675 20.211,39.827 15.308,39.878 18.65,39.898 16.324,39.919 40.505,40.437 28.823,40.462 38.522,40.462 1.821,40.488 2.659,40.488 4.031,40.488 5.504,40.488 6.85,40.488 8.192,40.488 9.441,40.488 10.66,40.488 26.054,40.488 30.277,40.488 32.23,40.488 34.308,40.488 36.365,40.488 22.263,40.615 11.498,40.64 19.645,40.64 20.617,40.64 24.071,40.64 18.65,40.665 12.184,40.691 13.454,40.716 14.851,40.716 15.978,40.716 0.576,40.724 17.112,40.742 24.955,40.742 27.47,40.742 42.467,40.97 17.055,41.456 18.65,41.456 0.576,41.639 20.206,41.639 15.371,41.664 3.175,41.838 5.191,41.838 7.208,41.838 9.224,41.838 11.202,41.842 42.467,41.927 25.209,42.023 27.309,42.056 29.41,42.056 31.51,42.056 33.611,42.056 35.711,42.064 37.812,42.076 39.912,42.076 0.576,42.426 20.206,42.596 15.371,42.621 12.256,42.627 2.167,42.755 4.183,42.755 6.2,42.755 8.216,42.755 10.232,42.754 42.467,42.918 26.259,42.96 28.36,42.972 30.46,42.972 32.561,42.972 34.661,42.96 36.762,42.993 38.862,42.993 40.962,42.993 24.159,43.023 0.576,43.315 20.206,43.586 15.371,43.612 3.175,43.671 5.191,43.671 7.208,43.671 9.224,43.671 11.24,43.671 42.467,43.807 25.209,43.857 27.309,43.889 29.41,43.889 31.51,43.889 33.611,43.889 35.711,43.897 37.812,43.909 39.912,43.909 0.576,44.475 20.206,44.475 15.371,44.501 2.167,44.588 4.183,44.588 6.2,44.588 8.216,44.588 10.232,44.588 12.172,44.598 42.467,44.594 26.259,44.793 28.36,44.806 30.46,44.806 32.561,44.806 34.661,44.794 36.762,44.826 38.862,44.826 40.962,44.826 24.159,44.902 20.206,45.263 15.371,45.288 42.467,45.509 0.767,45.524 41.699,46.077 30.708,46.147 31.624,46.147 32.54,46.147 33.456,46.147 34.372,46.147 35.288,46.147 36.204,46.147 37.12,46.147 38.036,46.147 38.952,46.147 39.868,46.147 40.784,46.147 1.245,46.177 2.161,46.177 3.077,46.177 3.992,46.177 4.908,46.177 5.824,46.177 6.74,46.177 7.656,46.177 8.572,46.177 9.487,46.177 10.403,46.177 11.319,46.177 12.432,46.177 13.529,46.177 14.282,46.177 15.305,46.177 20.219,46.177 21.223,46.177 21.971,46.177 23.068,46.177 24.181,46.177 25.211,46.177 26.127,46.177 27.043,46.177 27.96,46.177 28.876,46.177 29.792,46.177
  other v2: 27.597,6.532
GPIO2: CN1.8 SB25.2 | length 4
  Bottom Layer w0.2: CN1.8@6.398,29.978 10.298,29.978 10.382,29.895
GPIO3/BOOT0: CN1.9 R1.1 U1.22 | length 29.1
  Top Layer w0.2: v2(10.452,28.743) 10.471,28.762 R1.1@11.319,28.762 ; U1.22@20.264,34 20.264,35.862 v1(20.308,35.906) ; v1@20.295,35.753 20.33,35.789 v1@20.33,35.837
  Bottom Layer w0.2: CN1.9@2.334,28.708 3.991,28.708 4.636,29.353 8.547,29.353 9.157,28.743 v2(10.452,28.743) 10.85,28.346 16.951,28.346 18.377,29.772 18.377,32.985 17.945,33.417 17.945,35.754 18.463,36.271 19.943,36.271 v1(20.308,35.906)
GPIO5/JTMS/SWDIO: CN1.13 R2.2 SB41.2 U1.19 | length 88.8
  Top Layer w0.2: U1.19@21.764,34 21.764,34.82 23.458,36.515 v1(23.458,36.522)
  Internal 1 w0.21: v1(14.886,22.877) 14.869,22.859 14.869,15.28 14.897,15.251 14.897,14.596 15.888,13.605 v2(15.888,11.497) ; v1(28.08,22.216) 28.544,22.679 28.544,22.883 29.101,23.44 29.101,23.906 29.443,24.248 29.575,24.248 29.934,24.608 29.934,25.238 29.528,25.645 29.528,26.94 30.493,27.905 30.493,35.551 v1(30.061,35.982)
  Internal 1 w0.254: v2(19.622,11.471) 19.726,11.367 19.726,11.12 21.381,9.465 25.948,9.465 26.641,8.772 26.641,5.445 28.103,3.982 28.744,3.982 28.816,3.911 30.731,3.911 v2(30.795,3.975)
  Bottom Layer w0.2: CN1.13@2.334,26.168 4.067,26.168 4.712,26.813 9.894,26.813 ; v1(23.458,36.522) 23.814,36.877 29.167,36.877 v1(30.061,35.982) ; v2(30.795,3.975) 30.807,3.975 31.242,4.41 SB41.2@31.778,4.41
  Bottom Layer w0.21: 9.894,26.813 11.824,26.813 14.886,23.751 v1(14.886,22.877) 14.961,22.802 14.961,22.61 15.481,22.089 25.205,22.089 25.646,22.53 27.766,22.53 v1(28.08,22.216) ; v2(15.888,11.497) v2@19.564,11.497 ; R2.2@19.605,10.328 19.605,11.455 v2(19.622,11.471)
GPIO6/JTCK/SWCLK: CN1.15 R3.2 SB42.2 U1.18 | length 83.6
  Top Layer w0.2: U1.18@22.264,34 22.264,34.577 23.311,35.624 23.724,35.624 v1(23.742,35.642)
  Internal 1 w0.21: v1(14.237,22.022) 14.312,21.947 14.312,21.717 14.325,21.704 14.325,14.609 15.075,13.859 15.075,10.811 v2(15.101,10.786) ; v1(27.953,35.627) 28.969,35.627 29.655,34.941 29.655,28.185 28.69,27.219 28.69,23.892 v1@28.08,23.282
  Internal 1 w0.254: v2(20.811,11.467) 22.022,10.257 26.978,10.257 27.398,10.676 v2@27.398,10.684
  Internal 2 w0.21: v2(15.101,10.786) 20.13,10.786 v2(20.811,11.467)
  Bottom Layer w0.2: CN1.15@2.334,24.898 3.991,24.898 4.636,25.543 9.716,25.543 ; v1(23.742,35.642) 23.752,35.632 25.362,35.632 25.638,35.356 27.574,35.356 27.845,35.627 v1(27.953,35.627) ; v2(27.424,10.776) 27.476,10.724 31.773,10.724 31.823,10.674 SB42.2@31.838,10.674
  Bottom Layer w0.21: 9.716,25.543 10.173,26 11.773,26 14.085,23.689 14.085,22.139 14.27,21.954 15.107,21.954 15.332,21.729 25.355,21.729 25.534,21.909 26.917,21.909 27.165,21.661 28.549,21.661 28.842,21.954 28.842,23.003 28.563,23.282 v1(28.105,23.282) ; v2(20.811,11.467) 20.887,11.467 R3.2@20.887,10.328
GPIO15/OSC32_IN: CN1.33 SB37.2 | length 44.6
  Internal 1 w0.21: v2(25.591,15.485) 25.591,15.993 25.261,16.323 25.261,17.186 25.616,17.542 25.616,18.634 25.972,18.99 26.658,18.99 27.085,19.417 27.085,24.142 27.877,24.933 27.877,27.425 28.058,27.606 28.058,29.539 28.759,30.24 28.759,31.477 v1(28.038,32.198)
  Bottom Layer w0.2: CN1.33@2.334,13.468 3.737,13.468 4.382,14.113 10.584,14.113 13.372,16.9 24.734,16.9 25.591,16.043 v2(25.591,15.485)
GPIO16/OSC32_OUT: CN1.35 SB38.2 | length 43.5
  Internal 1 w0.21: v1(21.222,14.875) 21.222,16.983 21.628,17.39 v1(21.628,18.888) ; v1(26.15,19.625) 26.708,20.184 26.708,24.349 27.496,25.137 27.496,27.067 27.293,27.27 27.293,28.392 v1(27.32,28.42)
  Bottom Layer w0.2: CN1.35@2.334,12.198 3.966,12.198 4.61,12.843 9.815,12.843 11.67,14.697 16.259,14.697 16.448,14.885 21.212,14.885 v1(21.222,14.875) ; v1(28.009,30.856) 28.009,30.099 28.146,29.962
  Bottom Layer w0.21: v1(21.628,18.888) 23.025,20.285 25.489,20.285 v1(26.15,19.625) ; v1(27.32,28.42) 28.788,28.42 28.911,28.543 28.911,29.197 28.146,29.962 ; v1(28.009,30.856) v1@28.11,30.755
GPIO17: CN1.36 SB11.1 | length 4.1
  Bottom Layer w0.2: CN1.36@6.398,12.198 6.45,12.25 10.349,12.25 10.422,12.177 SB11.1@10.424,12.177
